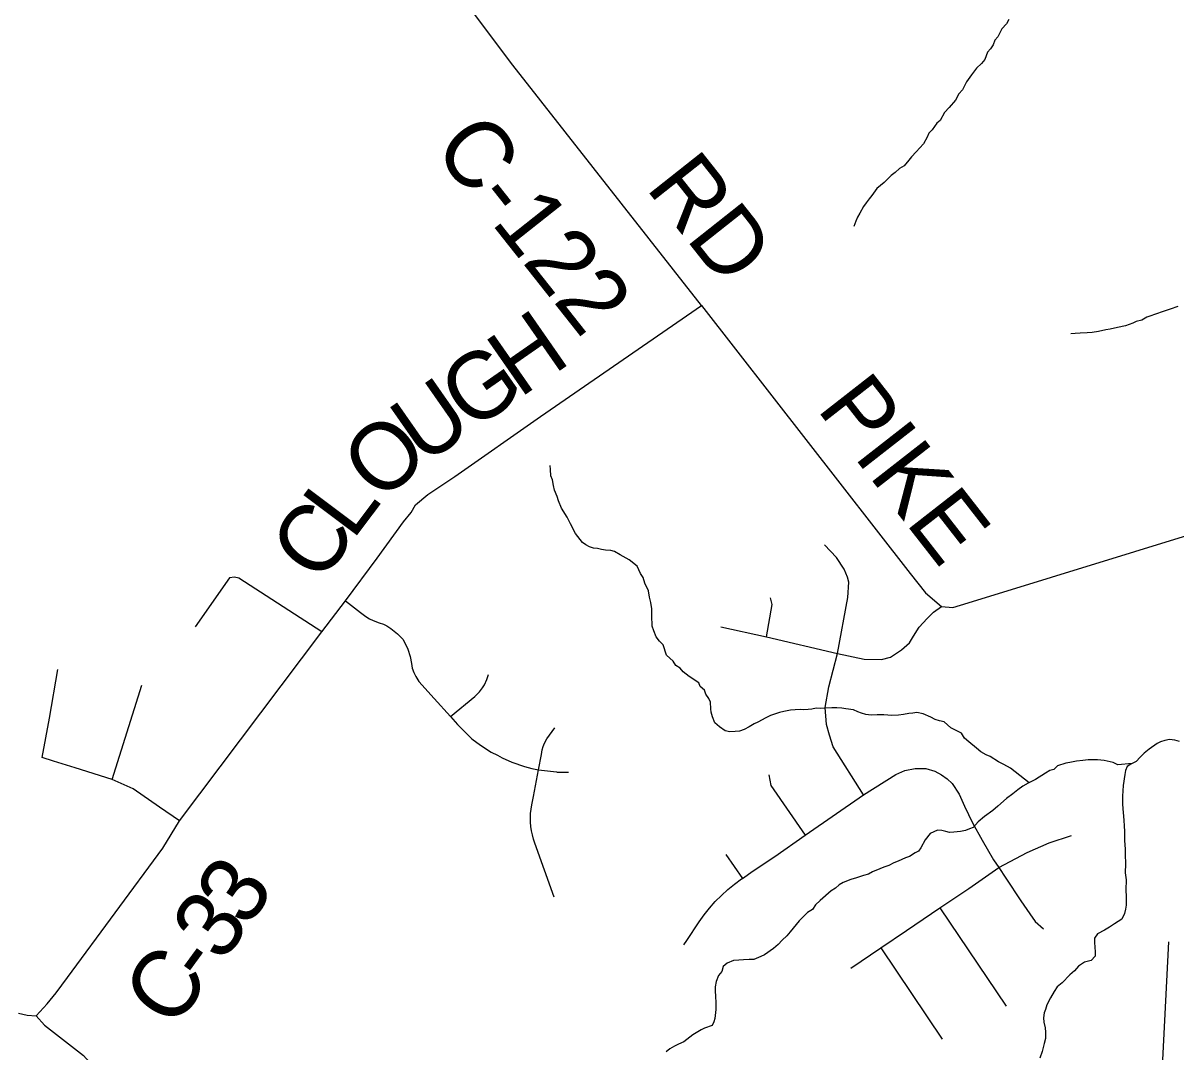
# Model space of a CAD drawing. Extents: x 0 to 34, y 0 to 22.
# Drawn here: x 3.128 to 4.106, y 16.016 to 16.889 of the extents above; entities that cross this region are included whole.
import ezdxf

# ---------------------------------------------------------------- set-up
doc = ezdxf.new("R2010")
doc.units = 0
for name, color, linetype in [('GM_X_County_Road', 7, 'Continuous'), ('GM_X_County_Road_Text', 7, 'Continuous'), ('GM_X_Minor_River', 7, 'Continuous'), ('GM_X_Township_Road', 7, 'Continuous')]:
    doc.layers.add(name, color=color, linetype=linetype)

msp = doc.modelspace()

# ---------------------------------------------------------------- linework, layer by layer
at = {"layer": 'GM_X_County_Road'}
for points in [[(3.70341, 16.64882), (3.54344, 16.85268), (3.30515, 17.17023), (3.29011, 17.19339)], [(3.12391, 16.04828), (3.13111, 16.04659), (3.13895, 16.04607), (3.14806, 16.05634), (3.15568, 16.06576), (3.16553, 16.07868), (3.24618, 16.18828), (3.26049, 16.2117), (3.38111, 16.37207), (3.40131, 16.39818), (3.42806, 16.43441), (3.45057, 16.46537), (3.457, 16.47308), (3.4606, 16.47973), (3.47107, 16.48856), (3.49421, 16.50389), (3.56681, 16.55472), (3.70341, 16.64882), (3.88042, 16.42139), (3.89348, 16.40507), (3.90699, 16.39334), (3.91682, 16.3927), (3.92981, 16.39654), (4.21243, 16.48369)]]:
    msp.add_lwpolyline(points, dxfattribs=at)
at = {"layer": 'GM_X_Minor_River'}
for points in [[(3.96415, 16.89153), (3.96219, 16.88776), (3.95832, 16.88365), (3.95478, 16.87687), (3.95245, 16.87387), (3.95087, 16.87009), (3.94853, 16.86671), (3.94619, 16.86371), (3.94381, 16.85767), (3.94109, 16.85429), (3.93684, 16.85019), (3.93257, 16.84456), (3.92829, 16.83855), (3.92475, 16.83177), (3.92165, 16.8284), (3.9189, 16.82313), (3.91347, 16.81676), (3.9096, 16.81265), (3.90606, 16.80586), (3.90298, 16.80364), (3.89909, 16.798), (3.89638, 16.79501), (3.8948, 16.79161), (3.89166, 16.78597), (3.88857, 16.7826), (3.88547, 16.77923), (3.8816, 16.77512), (3.87926, 16.77211), (3.87538, 16.76724), (3.87154, 16.76503), (3.86769, 16.76167), (3.86422, 16.75907), (3.85842, 16.75309), (3.85225, 16.74826), (3.84797, 16.74225), (3.84582, 16.73925), (3.8432, 16.73589), (3.84097, 16.73287), (3.83783, 16.72722), (3.83587, 16.72383), (3.83445, 16.72048), (3.8327, 16.71591)], [(4.10757, 16.648), (4.10107, 16.64583), (4.0961, 16.64402), (4.08769, 16.64112), (4.08462, 16.64003), (4.08119, 16.63895), (4.07696, 16.63637), (4.07238, 16.63531), (4.06931, 16.63384), (4.06319, 16.63166), (4.05633, 16.63026), (4.05022, 16.62885), (4.04641, 16.62816), (4.0403, 16.62674), (4.03497, 16.62608), (4.03078, 16.62577), (4.02469, 16.6255), (4.02051, 16.62519), (4.0167, 16.62488)], [(3.58461, 16.47695), (3.58205, 16.48307), (3.58098, 16.4869), (3.57879, 16.49226), (3.57771, 16.49608), (3.57703, 16.50103), (3.57557, 16.50447), (3.57528, 16.5098), (3.57496, 16.51323)], [(3.98152, 16.24395), (3.96565, 16.25628), (3.96, 16.25942), (3.95548, 16.26178), (3.94833, 16.26608), (3.94493, 16.26766), (3.94041, 16.27002), (3.93666, 16.27313), (3.93029, 16.27856), (3.92654, 16.28167), (3.92395, 16.2859), (3.91491, 16.29062), (3.90929, 16.29566), (3.9055, 16.29648), (3.90172, 16.29769), (3.89795, 16.29966), (3.89153, 16.30243), (3.88623, 16.30366), (3.8828, 16.30296), (3.87937, 16.30264), (3.8748, 16.30196), (3.8706, 16.30128), (3.8649, 16.301), (3.85806, 16.3015), (3.85236, 16.3016), (3.84741, 16.3013), (3.84286, 16.30176), (3.83908, 16.30297), (3.83605, 16.30416), (3.83228, 16.30575), (3.82583, 16.30662), (3.82242, 16.30706), (3.81824, 16.30751), (3.81406, 16.30759), (3.80797, 16.30731), (3.80417, 16.307), (3.80075, 16.30706), (3.79693, 16.30637), (3.79388, 16.30604), (3.79008, 16.30573), (3.78705, 16.30616), (3.78286, 16.30585), (3.77905, 16.30554), (3.77333, 16.3045), (3.76951, 16.30343), (3.76186, 16.3009), (3.75803, 16.29907), (3.75113, 16.29539), (3.74806, 16.29392), (3.74384, 16.29133), (3.73962, 16.28913), (3.73579, 16.28767), (3.73198, 16.28736), (3.72742, 16.28706), (3.72363, 16.28788), (3.71874, 16.29139), (3.71462, 16.29488), (3.7128, 16.29986), (3.71173, 16.30368), (3.7114, 16.30672), (3.71111, 16.31243), (3.70964, 16.3155), (3.70704, 16.31896), (3.70596, 16.3224), (3.70221, 16.32551), (3.70112, 16.32857), (3.69285, 16.33404), (3.68797, 16.33792), (3.68536, 16.34101), (3.6816, 16.34336), (3.67938, 16.34719), (3.67376, 16.35224), (3.67087, 16.36103), (3.66788, 16.36412), (3.6649, 16.36759), (3.66308, 16.37295), (3.66163, 16.37677), (3.6614, 16.3859), (3.66112, 16.39161), (3.66045, 16.39694), (3.65938, 16.40152), (3.65833, 16.40686), (3.6554, 16.41337), (3.65396, 16.41796), (3.65173, 16.42142), (3.6488, 16.42755), (3.64204, 16.43299), (3.63451, 16.43731), (3.62961, 16.44005), (3.62659, 16.44087), (3.62203, 16.44132), (3.61862, 16.44176), (3.61521, 16.44258), (3.6118, 16.44302), (3.6084, 16.44422), (3.60538, 16.4458), (3.60237, 16.44775), (3.59642, 16.45546), (3.59237, 16.46351), (3.58943, 16.46926), (3.58461, 16.47695)], [(4.10898, 16.27886), (4.10519, 16.28006), (4.10064, 16.28052), (4.09645, 16.27984), (4.09301, 16.27875), (4.08994, 16.27729)], [(4.08994, 16.27729), (4.0834, 16.27246), (4.07916, 16.26912), (4.07568, 16.26576), (4.0722, 16.26201), (4.0676, 16.25982), (4.06452, 16.25759), (4.06332, 16.25419), (4.06251, 16.25078), (4.06121, 16.24168), (4.06068, 16.23257), (4.06057, 16.22611), (4.06088, 16.22192), (4.06153, 16.21545), (4.06185, 16.21202), (4.06216, 16.20745), (4.06246, 16.20251), (4.06232, 16.19453), (4.06265, 16.19148), (4.06296, 16.18729), (4.06289, 16.18311), (4.06314, 16.17513), (4.06301, 16.16752), (4.06367, 16.16143), (4.06353, 16.15307), (4.06381, 16.14699), (4.06369, 16.14015), (4.06325, 16.13673), (4.06243, 16.13294), (4.06007, 16.12804), (4.05392, 16.12435), (4.04969, 16.12138), (4.04546, 16.1188), (4.03933, 16.11586), (4.03699, 16.1121), (4.03693, 16.10868), (4.03723, 16.10412), (4.03756, 16.10069), (4.03749, 16.09689), (4.03401, 16.09315), (4.02828, 16.09173), (4.02328, 16.0884), (4.01979, 16.08428), (4.01594, 16.08092), (4.00936, 16.0742), (4.00512, 16.07085), (4.00277, 16.06671), (3.99964, 16.06144), (3.9965, 16.05542), (3.9953, 16.05164), (3.9941, 16.04862), (3.99365, 16.04444), (3.99397, 16.04064), (3.99503, 16.03606), (3.99535, 16.03225), (3.99526, 16.02693), (3.99405, 16.02277), (3.99241, 16.01596), (3.99042, 16.01029)], [(4.06873, 16.26036), (4.05656, 16.25925), (4.0528, 16.26122), (4.04522, 16.26287), (4.03952, 16.26335), (4.03154, 16.26349), (4.02697, 16.26281), (4.02164, 16.26214), (4.01592, 16.2611), (4.01248, 16.2604), (4.0056, 16.25824), (4.00251, 16.25525), (3.99907, 16.25417), (3.99523, 16.25196), (3.98678, 16.24679), (3.98064, 16.24347), (3.97604, 16.24089), (3.97181, 16.23792), (3.96757, 16.23458), (3.96218, 16.23049), (3.95485, 16.22416), (3.9506, 16.22043), (3.94367, 16.21523), (3.93828, 16.21076), (3.93401, 16.2059), (3.93095, 16.20481), (3.92751, 16.20335), (3.92331, 16.20266), (3.9176, 16.202), (3.91379, 16.20169), (3.91076, 16.2025), (3.90736, 16.20332), (3.90356, 16.20377), (3.89743, 16.20084), (3.89316, 16.19559), (3.88962, 16.18881), (3.88767, 16.1858), (3.88461, 16.18434), (3.88, 16.18138), (3.87656, 16.18029), (3.87042, 16.17736), (3.8666, 16.17591), (3.86238, 16.1737), (3.85817, 16.17226), (3.85473, 16.1708), (3.8486, 16.16824), (3.84515, 16.1664), (3.84095, 16.16533), (3.83483, 16.16316), (3.83024, 16.16172), (3.82374, 16.15918), (3.82029, 16.15734), (3.81719, 16.15435), (3.81336, 16.15214), (3.80409, 16.14393), (3.80023, 16.1402), (3.79751, 16.13645), (3.79328, 16.13386), (3.78632, 16.12676), (3.77856, 16.1174), (3.77584, 16.11402), (3.77197, 16.11029), (3.76849, 16.10655), (3.76463, 16.1032), (3.75694, 16.09801), (3.75387, 16.09654), (3.74775, 16.09399), (3.74395, 16.09405), (3.739, 16.09376), (3.73519, 16.09345), (3.73063, 16.09315), (3.72527, 16.09096), (3.7218, 16.08798), (3.72059, 16.08382), (3.71787, 16.08045), (3.71588, 16.07516), (3.71504, 16.07062), (3.71498, 16.06682), (3.7153, 16.06301), (3.71557, 16.05692), (3.71548, 16.0516), (3.7146, 16.04402), (3.71379, 16.04099), (3.71259, 16.03797), (3.70609, 16.0358), (3.70303, 16.03434), (3.69611, 16.0299), (3.68841, 16.02395), (3.68382, 16.02213), (3.68036, 16.02029), (3.67652, 16.01808), (3.67344, 16.01547)]]:
    msp.add_lwpolyline(points, dxfattribs=at)
at = {"layer": 'GM_X_Township_Road'}
for p, q in [((3.20328, 16.24674), (3.2285, 16.32661)), ((3.79129, 16.19933), (3.841, 16.23378)), ((3.76551, 16.18137), (3.79129, 16.19933)), ((3.72416, 16.18309), (3.7381, 16.16279)), ((3.90568, 16.13771), (3.96196, 16.05436)), ((3.83005, 16.08651), (3.85554, 16.10377)), ((3.85554, 16.10377), (3.90775, 16.02636))]:
    msp.add_line(p, q, dxfattribs=at)
for points in [[(3.81873, 16.35353), (3.82771, 16.40118), (3.8285, 16.41407), (3.82733, 16.41837), (3.82459, 16.42501), (3.81795, 16.43516), (3.8078, 16.44571)], [(3.38111, 16.37207), (3.31078, 16.41764), (3.307, 16.41843), (3.30282, 16.41771), (3.27365, 16.37626)], [(3.40131, 16.39818), (3.41397, 16.38838), (3.41868, 16.38484), (3.4218, 16.3829), (3.42492, 16.38151), (3.42991, 16.37964), (3.43352, 16.37839), (3.43643, 16.37714), (3.43813, 16.37604), (3.43982, 16.37493), (3.44558, 16.37028), (3.44742, 16.36831), (3.44984, 16.36561), (3.45171, 16.3627), (3.45435, 16.35715), (3.45615, 16.35098), (3.45719, 16.34505), (3.45802, 16.34117), (3.45927, 16.33749), (3.46086, 16.33403), (3.46364, 16.32973), (3.47667, 16.31527), (3.4904, 16.30027), (3.49629, 16.29333), (3.50332, 16.2863), (3.50852, 16.28124), (3.51587, 16.27576), (3.52495, 16.26994), (3.53022, 16.26718), (3.53431, 16.26505), (3.54256, 16.26151), (3.55317, 16.25784), (3.55941, 16.25611), (3.56523, 16.25493), (3.58027, 16.25306), (3.5809, 16.25299), (3.59043, 16.25292)], [(3.75859, 16.36759), (3.76325, 16.39527), (3.76209, 16.40079)], [(3.71992, 16.37618), (3.75859, 16.36759), (3.81873, 16.35353), (3.84138, 16.34884), (3.85623, 16.34845), (3.86365, 16.35041), (3.87302, 16.35666), (3.88005, 16.36251), (3.88318, 16.36837), (3.88825, 16.3758), (3.8949, 16.38321), (3.90036, 16.38868), (3.90699, 16.39334)], [(3.841, 16.23378), (3.81527, 16.2744), (3.81191, 16.28426), (3.8095, 16.29339), (3.8083, 16.30782), (3.81143, 16.32537), (3.81873, 16.35353)], [(3.26049, 16.2117), (3.24334, 16.22311), (3.22119, 16.23863), (3.20328, 16.24674), (3.17179, 16.25671), (3.15366, 16.26211), (3.14397, 16.26543), (3.1502, 16.29883), (3.15731, 16.34007)], [(3.4904, 16.30027), (3.51108, 16.31705), (3.51491, 16.32095), (3.51764, 16.32439), (3.51932, 16.32712), (3.52135, 16.33154), (3.52259, 16.33568)], [(3.57844, 16.14695), (3.56194, 16.1926), (3.56081, 16.19607), (3.55988, 16.19959), (3.55916, 16.20317), (3.55865, 16.20678), (3.55836, 16.21042), (3.55828, 16.21407), (3.55843, 16.21781), (3.55879, 16.22146), (3.55937, 16.22508), (3.56084, 16.23223), (3.56523, 16.25493), (3.56763, 16.26786), (3.56832, 16.27175), (3.56902, 16.27466), (3.57013, 16.27743), (3.57221, 16.28118), (3.579, 16.29047)], [(3.7605, 16.25076), (3.76215, 16.24171), (3.79129, 16.19933)], [(3.841, 16.23378), (3.8684, 16.25084), (3.87609, 16.25445), (3.88475, 16.25613), (3.89388, 16.25589), (3.90133, 16.25373), (3.9071, 16.25061), (3.91191, 16.24724), (3.916, 16.24315), (3.92201, 16.23426), (3.92657, 16.22416), (3.9333, 16.20998), (3.94148, 16.19532), (3.95109, 16.17849), (3.95566, 16.17201)], [(3.95566, 16.17201), (3.97964, 16.18468), (3.99851, 16.19297), (4.0175, 16.1991)], [(3.7381, 16.16279), (3.74734, 16.16913), (3.76551, 16.18137)], [(3.90568, 16.13771), (3.93036, 16.15427), (3.95566, 16.17201)], [(3.95566, 16.17201), (3.96167, 16.16286), (3.97441, 16.14363), (3.9821, 16.13257), (3.98663, 16.1263), (3.99364, 16.12007)], [(3.68838, 16.10632), (3.69106, 16.11019), (3.70144, 16.12582), (3.70567, 16.13183), (3.71023, 16.13759), (3.71509, 16.1431), (3.72025, 16.14834), (3.72568, 16.15329), (3.73138, 16.15793), (3.73732, 16.16225), (3.7381, 16.16279)], [(3.85554, 16.10377), (3.87735, 16.11853), (3.90568, 16.13771)], [(4.08239, 15.81272), (4.09405, 15.99209), (4.0999, 16.10906)], [(3.13895, 16.04607), (3.14583, 16.03823), (3.17898, 16.01249), (3.18851, 16.00169), (3.19656, 15.98496)]]:
    msp.add_lwpolyline(points, dxfattribs=at)

# ---------------------------------------------------------------- texts
at = {"layer": 'GM_X_County_Road_Text'}
for s, height, rotation, p in [('C-122', 0.056818, 308.35914, (3.47457, 16.78202)), ('RD', 0.056818, 308.35094, (3.65533, 16.74881)), ('H', 0.05682, 34.83234, (3.54898, 16.56972)), ('G', 0.05682, 34.83385, (3.50795, 16.54116)), ('U', 0.05682, 34.91264, (3.46696, 16.51256)), ('PIKE', 0.056818, 307.98314, (3.80043, 16.56121)), ('O', 0.05682, 41.35007, (3.43075, 16.48057)), ('L', 0.05682, 53.1181, (3.40734, 16.44883)), ('C', 0.05682, 53.53444, (3.37967, 16.41139)), ('3', 0.05682, 55.61535, (3.31791, 16.11977)), ('3', 0.05682, 54.17938, (3.29653, 16.09011)), ('-', 0.05682, 53.85489, (3.28257, 16.07099)), ('C', 0.05682, 53.77721, (3.25494, 16.03327))]:
    msp.add_text(s, height=height, rotation=rotation, dxfattribs=at).set_placement(p)

doc.saveas('drawing.dxf')
